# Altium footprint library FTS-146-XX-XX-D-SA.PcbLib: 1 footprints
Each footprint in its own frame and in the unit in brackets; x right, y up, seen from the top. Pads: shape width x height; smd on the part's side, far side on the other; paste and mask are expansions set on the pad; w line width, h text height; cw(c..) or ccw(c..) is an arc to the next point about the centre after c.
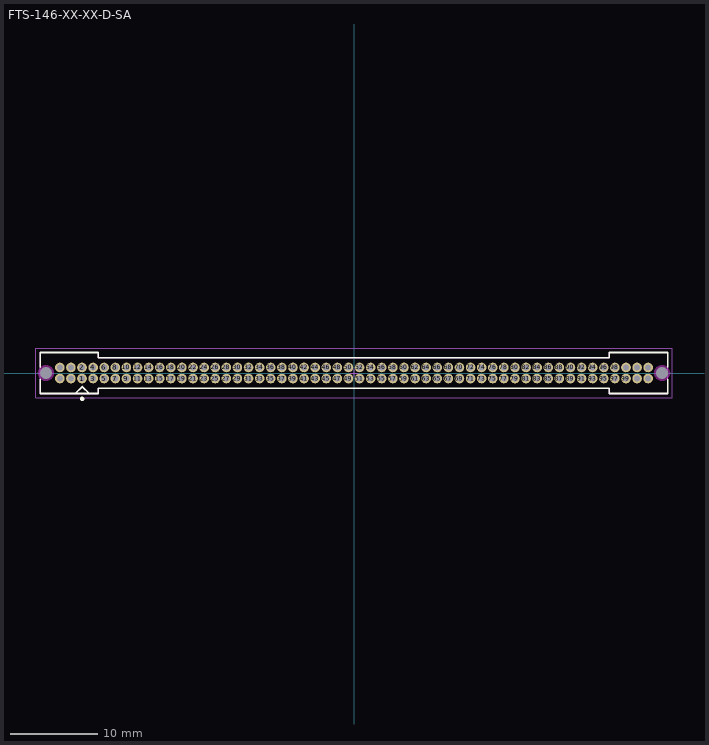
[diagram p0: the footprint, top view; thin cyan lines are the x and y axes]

## FTS-146-XX-XX-D-SA [mm] "1.27mm pitch, 92 pin, terminal strip; low profile, w/alignment pins, w/end shrouds, PTH"
height 4.32
pads (110):
  round 1.1 hole 0.7 mask+0: 1(-31.115,-0.635) 2(-31.115,0.635) 3(-29.845,-0.635) 4(-29.845,0.635) 5(-28.575,-0.635) 6(-28.575,0.635) 7(-27.305,-0.635) 8(-27.305,0.635) 9(-26.035,-0.635) 10(-26.035,0.635) 11(-24.765,-0.635) 12(-24.765,0.635) 13(-23.495,-0.635) 14(-23.495,0.635) 15(-22.225,-0.635) 16(-22.225,0.635) 17(-20.955,-0.635) 18(-20.955,0.635) 19(-19.685,-0.635) 20(-19.685,0.635) 21(-18.415,-0.635) 22(-18.415,0.635) 23(-17.145,-0.635) 24(-17.145,0.635) 25(-15.875,-0.635) 26(-15.875,0.635) 27(-14.605,-0.635) 28(-14.605,0.635) 29(-13.335,-0.635) 30(-13.335,0.635) 31(-12.065,-0.635) 32(-12.065,0.635) 33(-10.795,-0.635) 34(-10.795,0.635) 35(-9.525,-0.635) 36(-9.525,0.635) 37(-8.255,-0.635) 38(-8.255,0.635) 39(-6.985,-0.635) 40(-6.985,0.635) 41(-5.715,-0.635) 42(-5.715,0.635) 43(-4.445,-0.635) 44(-4.445,0.635) 45(-3.175,-0.635) 46(-3.175,0.635) 47(-1.905,-0.635) 48(-1.905,0.635) 49(-0.635,-0.635) 50(-0.635,0.635) 51(0.635,-0.635) 52(0.635,0.635) 53(1.905,-0.635) 54(1.905,0.635) 55(3.175,-0.635) 56(3.175,0.635) 57(4.445,-0.635) 58(4.445,0.635) 59(5.715,-0.635) 60(5.715,0.635) 61(6.985,-0.635) 62(6.985,0.635) 63(8.255,-0.635) 64(8.255,0.635) 65(9.525,-0.635) 66(9.525,0.635) 67(10.795,-0.635) 68(10.795,0.635) 69(12.065,-0.635) 70(12.065,0.635) 71(13.335,-0.635) 72(13.335,0.635) 73(14.605,-0.635) 74(14.605,0.635) 75(15.875,-0.635) 76(15.875,0.635) 77(17.145,-0.635) 78(17.145,0.635) 79(18.415,-0.635) 80(18.415,0.635) 81(19.685,-0.635) 82(19.685,0.635) 83(20.955,-0.635) 84(20.955,0.635) 85(22.225,-0.635) 86(22.225,0.635) 87(23.495,-0.635) 88(23.495,0.635) 89(24.765,-0.635) 90(24.765,0.635) 91(26.035,-0.635) 92(26.035,0.635) 93(27.305,-0.635) 94(27.305,0.635) 95(28.575,-0.635) 96(28.575,0.635) 97(29.845,-0.635) 98(29.845,0.635) 99(31.115,-0.635) 100(31.115,0.635) 101(-33.655,-0.635) 102(-33.655,0.635) 103(-32.385,-0.635) 104(-32.385,0.635) 105(32.385,-0.635) 106(32.385,0.635) 107(33.655,-0.635) 108(33.655,0.635)
  round 1 hole 1.35 unplated mask+0: 109(35.242,0) 110(-35.242,0)
Top Overlay:
  circle w0.25: c-31.1,-2.95 r0.125
  lines w0.2: -35.9,-0.7 -35.9,-2.35 -29.25,-2.35 -29.25,-1.75 29.2,-1.75 29.2,-2.35 35.9,-2.35 35.9,-0.7 ; -35.9,0.7 -35.9,2.35 -29.25,2.35 -29.25,1.75 29.2,1.75 29.2,2.35 35.9,2.35 35.9,0.7 ; -31.9,-2.35 -31.1,-1.55 -30.3,-2.35
Keep-Out Layer:
  pour cut-out: -34.335,0 -34.366,0.235 -34.457,0.454 -34.601,0.642 -34.789,0.786 -35.008,0.877 -35.243,0.908 -35.478,0.877 -35.697,0.786 -35.885,0.642 -36.029,0.454 -36.12,0.235 -36.151,0 -36.12,-0.235 -36.029,-0.454 -35.885,-0.642 -35.697,-0.786 -35.478,-0.877 -35.243,-0.908 -35.008,-0.877 -34.789,-0.786 -34.601,-0.642 -34.457,-0.454 -34.366,-0.235
  pour cut-out: 36.151,0 36.12,0.235 36.029,0.454 35.885,0.642 35.697,0.786 35.478,0.877 35.243,0.908 35.008,0.877 34.789,0.786 34.601,0.642 34.457,0.454 34.366,0.235 34.335,0 34.366,-0.235 34.457,-0.454 34.601,-0.642 34.789,-0.786 35.008,-0.877 35.243,-0.908 35.478,-0.877 35.697,-0.786 35.885,-0.642 36.029,-0.454 36.12,-0.235
Mechanical 12:
  lines w0.001: -35.9,-2.349 -29.25,-2.349 -29.25,-1.74 29.2,-1.74 29.2,-2.35 35.9,-2.35 35.9,2.35 29.2,2.35 29.2,1.75 -29.25,1.75 -29.25,2.35 -35.9,2.35 -35.9,-2.349
Mechanical 13:
  lines w0.1: -35.9,-2.349 -29.25,-2.349 -29.25,-1.74 29.2,-1.74 29.2,-2.35 35.9,-2.35 35.9,2.35 29.2,2.35 29.2,1.75 -29.25,1.75 -29.25,2.35 -35.9,2.35 -35.9,-2.349
  text ".Designator" at 0.254,0.127 h1.52
Mechanical 15:
  lines w0.05: -0.5,0 0.5,0 ; 0,-0.5 0,0.5 ; -36.4,-2.85 36.4,-2.85 36.4,2.85 -36.4,2.85 -36.4,-2.85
